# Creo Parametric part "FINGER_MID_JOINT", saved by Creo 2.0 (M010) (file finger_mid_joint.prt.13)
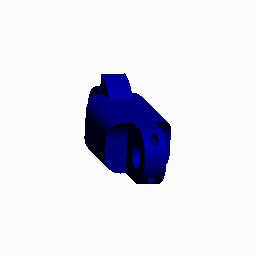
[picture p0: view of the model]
Units: Inch lbm Second (Pro/E Default); INCH, POUND, SECS

Created from: INLBS_PART_SOLID.PRT

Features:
  1. datum plane "RIGHT"
  2. datum plane "TOP"
  3. datum plane "FRONT"
  4. coordinate system
  5. sketch "Sketch 1"
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
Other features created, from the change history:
  extrusion "Extrude 1"
  sketch "Sketch 2"
  extrusion "Extrude 2"
  round "Round 1"
  round "Round 2"
  sketch "Sketch 3"
  extruded cut "Extrude 3"
  mirror "Mirror 1" (2 times)
  sketch "Sketch 3 (2)"
  extruded cut "Extrude 4"
  mirror "Mirror 2"
  extruded cut "Extrude 5"
  mirror "Mirror 3"
  extruded cut "Extrude 6"
  sketch "Sketch 4"
  extrusion "Extrude 7"
  sketch "Sketch 5"
  extruded cut "Extrude 8"
  sketch "Sketch 6"
  extruded cut "Extrude 9"
  sketch "Sketch 7"
  extrusion "Extrude 10"

Surfaces: 21 cylinder, 20 plane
